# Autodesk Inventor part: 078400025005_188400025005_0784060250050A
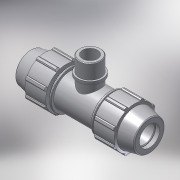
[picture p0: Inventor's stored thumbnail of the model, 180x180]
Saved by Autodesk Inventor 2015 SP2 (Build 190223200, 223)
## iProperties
Created: 2017-02
Part Number: 078400025005_188400025005_0784060250050A
Material: PVC-Piping
Description: PLASSON TEE WITH THREADED MALE OFFTAKE 25-1/2"-25
Document SubType Name: Modeling
Designer: KIM
Mass: 92.6774 g
Surface Area: 199.44 cm^2
Volume: 66.1981 cm^3
Density: 1.4 g/cm^3
Appearance: Smooth - White
Author: Кирилл
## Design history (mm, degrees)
derived "07840.ipt"
feature "Solid1::07840.ipt"
feature "Solid2::07840.ipt"
tag "TaggingFeature1"
body "Solid1"
body "Solid2"
other parameters: "d2" = 25, "d4" = 6.08333, "d5" = 17.52, "d7" = 54, "d11" = 2.43333, "d13" = 120 deg, "d14" = 37.5, "d15" = 12 deg, "d16" = 46.98, "d18" = 1.25, "d19" = 35 deg, "d20" = 17.5 deg, "d21" = 50.22, "d23" = 0, "d25" = 360 deg, "d27" = 1.08, "d33" = 0.5, "d42" = 26.28, "d43" = 1.62, "d46" = 0.75, "d68" = 2.43333, "d72" = 48, "d73" = 20.955, "d74" = 17, "d75" = 24.09825, "d76" = 14.6685, "d77" = 20.4, "d80" = 0.62865, "d91" = 40.5, "d93" = 58, "d95" = 22.5, "d99" = 146, "d101" = 0, "d103" = 0, "d105" = 0, "d_" = 25, "E_" = 54, "A_" = 48, "l_" = 58, "l_2" = 17, "H_" = 146, "R_" = 20.955
